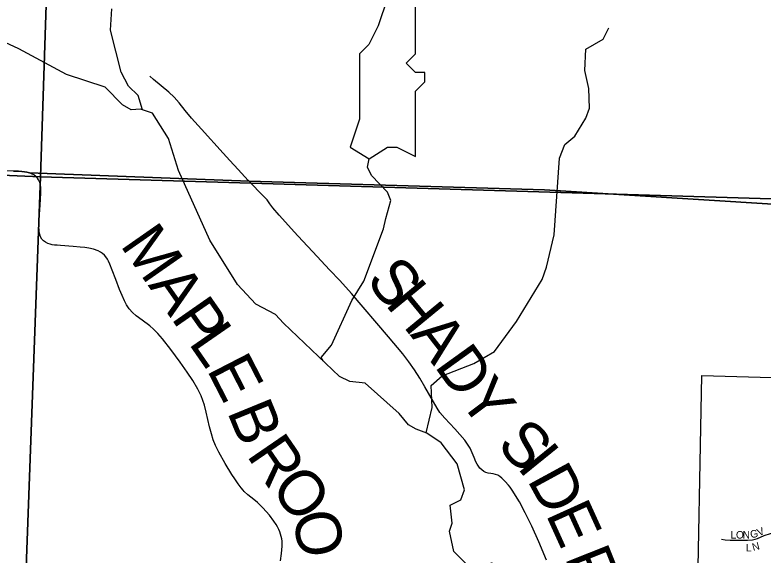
# Model space of a CAD drawing. Extents: x 0 to 34, y 0 to 22.
# Drawn here: x 26.645 to 27.584, y 17.84 to 18.518 of the extents above; entities that cross this region are included whole.
import ezdxf

# ---------------------------------------------------------------- set-up
doc = ezdxf.new("R2010")
doc.units = 0
for name, color, linetype in [('GM_X_City_Street', 7, 'Continuous'), ('GM_X_City_Street_Text', 7, 'Continuous'), ('GM_X_Corporation', 7, 'Continuous'), ('GM_X_Minor_Lake', 7, 'Continuous'), ('GM_X_Minor_River', 7, 'Continuous'), ('GM_X_Section', 7, 'Continuous'), ('GM_X_Township', 7, 'Continuous'), ('GM_X_Township_Road', 7, 'Continuous'), ('GM_X_Township_Road_Text', 7, 'Continuous')]:
    doc.layers.add(name, color=color, linetype=linetype)

msp = doc.modelspace()

# ---------------------------------------------------------------- linework, layer by layer
at = {"layer": 'GM_X_City_Street'}
msp.add_lwpolyline([(27.5316, 17.86006), (27.53621, 17.8594), (27.54244, 17.859), (27.55182, 17.85887), (27.56434, 17.85906), (27.57056, 17.85951), (27.57361, 17.86008), (27.57659, 17.86099), (27.58524, 17.86465), (27.59314, 17.86742), (27.59554, 17.86765), (27.60988, 17.86768), (27.63074, 17.8673)], dxfattribs=at)
at = {"layer": 'GM_X_Corporation'}
msp.add_lwpolyline([(26.90696, 16.92457), (26.90869, 17.23113), (26.9676, 17.24455), (26.96758, 17.23868), (27.13632, 17.27124), (27.45355, 17.35652), (27.45221, 17.36927), (27.4769, 17.37407), (27.40895, 17.45881), (27.41908, 17.4656), (27.42835, 17.45306), (27.5213, 17.52673), (27.43555, 17.68311), (27.50076, 17.73762), (27.50706, 18.06564), (27.60948, 18.06256)], dxfattribs=at)
msp.add_lwpolyline([(26.90696, 16.92457), (26.90869, 17.23113), (26.9676, 17.24455), (26.96758, 17.23868), (27.13632, 17.27124), (27.45355, 17.35652), (27.45221, 17.36927), (27.4769, 17.37407), (27.40895, 17.45881), (27.41908, 17.4656), (27.42835, 17.45306), (27.5213, 17.52673), (27.43555, 17.68311), (27.50076, 17.73762), (27.50706, 18.06564), (27.60948, 18.06256)], dxfattribs=at)
at = {"layer": 'GM_X_Minor_Lake'}
for points in [[(27.12245, 18.75022), (27.11268, 18.75011), (27.11268, 18.73841), (27.10097, 18.72671), (27.10097, 18.71501), (27.10097, 18.6799), (27.10097, 18.66819), (27.10096, 18.64479), (27.10096, 18.62138), (27.10096, 18.60968), (27.10096, 18.58627), (27.10095, 18.56287), (27.11266, 18.53946), (27.10095, 18.50437), (27.08924, 18.48097), (27.07754, 18.46926), (27.07754, 18.44586), (27.07753, 18.42245), (27.07753, 18.38734), (27.06582, 18.35223), (27.08951, 18.33736)], [(27.08951, 18.33736), (27.11264, 18.35223), (27.12433, 18.35223), (27.14773, 18.34053), (27.14773, 18.35223), (27.14773, 18.37563), (27.14774, 18.39904), (27.14774, 18.41074), (27.14774, 18.42245), (27.15944, 18.43415), (27.15945, 18.44585), (27.14774, 18.44585), (27.13604, 18.45756), (27.14774, 18.46926), (27.14775, 18.48096), (27.14775, 18.49266), (27.14775, 18.51605), (27.14775, 18.53946)]]:
    msp.add_lwpolyline(points, dxfattribs=at)
at = {"layer": 'GM_X_Minor_River'}
for points in [[(26.80545, 18.39887), (26.79994, 18.41687), (26.78776, 18.42856), (26.77856, 18.44595), (26.76538, 18.49898), (26.76675, 18.52554)], [(27.1957, 17.8449), (27.19025, 17.87029), (27.19361, 17.88017), (27.19121, 17.90291), (27.20481, 17.90943), (27.20929, 17.92198), (27.20001, 17.95492), (27.18016, 17.98098), (27.1619, 17.99339), (27.14862, 17.99824), (27.13911, 18.0035), (27.12729, 18.01785), (27.08463, 18.05591), (27.0653, 18.05807), (27.05238, 18.06445), (26.98228, 18.13118), (26.97237, 18.14212), (26.94767, 18.15488), (26.92442, 18.17977), (26.89, 18.23533), (26.85049, 18.32272), (26.83814, 18.36285), (26.81788, 18.3946), (26.80269, 18.39982), (26.79133, 18.399), (26.78031, 18.40538), (26.75858, 18.42725), (26.70999, 18.44329), (26.65032, 18.47556), (26.59372, 18.50141)], [(27.31194, 18.20134), (27.32189, 18.24208), (27.32843, 18.33844), (27.33506, 18.35558), (27.34743, 18.36595), (27.36157, 18.38847), (27.36597, 18.40103), (27.36533, 18.42566), (27.36017, 18.44835), (27.36141, 18.47491), (27.38321, 18.48765), (27.39025, 18.50176)], [(27.03184, 18.084), (27.02951, 18.08821), (27.04231, 18.10383), (27.06776, 18.15973), (27.08316, 18.1841), (27.10781, 18.24948), (27.11038, 18.26277), (27.1167, 18.28518), (27.11247, 18.29578), (27.09265, 18.31652), (27.08767, 18.32711), (27.08951, 18.33736)], [(27.1611, 17.99368), (27.16855, 18.02529), (27.16726, 18.05297), (27.18121, 18.06518), (27.22091, 18.08058), (27.24697, 18.09553), (27.27442, 18.13323), (27.30672, 18.18614), (27.31194, 18.20134)], [(27.1957, 17.8449), (27.21128, 17.8294), (27.22037, 17.82946), (27.22873, 17.82534), (27.23479, 17.82614), (27.24309, 17.83074), (27.2484, 17.82926), (27.25147, 17.82435), (27.26898, 17.81118), (27.28113, 17.80557), (27.28947, 17.80448), (27.29407, 17.79654), (27.29646, 17.77949), (27.29884, 17.76282), (27.30719, 17.75983)]]:
    msp.add_lwpolyline(points, dxfattribs=at)
at = {"layer": 'GM_X_Section'}
for points in [[(25.7174, 19.34531), (26.71012, 19.30514), (26.67748, 18.31474), (25.68285, 18.35754)], [(27.70209, 19.27644), (27.6773, 18.28453), (26.67748, 18.31474), (26.71012, 19.30514)], [(26.67748, 18.31474), (26.63943, 17.27671), (26.13693, 17.28272), (26.13573, 17.24141), (25.63163, 17.25763), (25.68285, 18.35754)], [(26.67748, 18.31474), (27.6773, 18.28453), (27.62712, 17.24067), (26.63943, 17.27671)]]:
    msp.add_lwpolyline(points, close=True, dxfattribs=at)
at = {"layer": 'GM_X_Township'}
for points in [[(26.64338, 18.32213), (26.64994, 18.32195), (26.65415, 18.32164), (26.6574, 18.3212), (26.66046, 18.32066), (26.66345, 18.31987), (26.93903, 18.30939), (27.3097, 18.29835), (27.60273, 18.28017), (27.85085, 18.27245), (28.03523, 18.26605), (28.13527, 18.2617), (28.25997, 18.25738), (28.66555, 18.2443), (28.72626, 19.93416)], [(28.59551, 16.41415), (28.59908, 16.58872), (28.59988, 16.61088), (28.63677, 17.49807), (28.63701, 17.50604), (28.6433, 17.85758), (28.66555, 18.2443), (28.25997, 18.25738), (28.13527, 18.2617), (28.03523, 18.26605), (27.85085, 18.27245), (27.60273, 18.28017), (27.3097, 18.29835), (26.93903, 18.30939), (26.66345, 18.31987), (26.66046, 18.32066), (26.6574, 18.3212), (26.65415, 18.32164), (26.64994, 18.32195), (26.64338, 18.32213)]]:
    msp.add_lwpolyline(points, dxfattribs=at)
at = {"layer": 'GM_X_Township_Road'}
for points in [[(26.93842, 18.31003), (26.93803, 18.31043), (26.92529, 18.32403), (26.91477, 18.33545), (26.9064, 18.34462), (26.87939, 18.37463), (26.86691, 18.38848), (26.85886, 18.39795), (26.85115, 18.40771), (26.84503, 18.41473), (26.83832, 18.42119), (26.82875, 18.42911), (26.81918, 18.43705), (26.81459, 18.44121)], [(26.66534, 18.31912), (26.66346, 18.31987), (26.66045, 18.32066), (26.6574, 18.3212), (26.65415, 18.32164), (26.64994, 18.32195), (26.64337, 18.32213), (26.5923, 18.32397), (26.5706, 18.32489), (26.55514, 18.32585), (26.53747, 18.3271), (26.52526, 18.32795), (26.51587, 18.32844), (26.50008, 18.32926), (26.48991, 18.32965), (26.48619, 18.33005)], [(26.93173, 17.92155), (26.93151, 17.9218), (26.92894, 17.92474), (26.92519, 17.92968), (26.92099, 17.93589), (26.91722, 17.94156), (26.90886, 17.95504), (26.90101, 17.9694), (26.89689, 17.97771), (26.89403, 17.98498), (26.89186, 17.99235), (26.88948, 18.00135), (26.88532, 18.0195), (26.88298, 18.0285), (26.88105, 18.03439), (26.87892, 18.04026), (26.87461, 18.04862), (26.86831, 18.05918), (26.86152, 18.06958), (26.85242, 18.08215), (26.84089, 18.09825), (26.83065, 18.11146), (26.82471, 18.11847), (26.81932, 18.12387), (26.81473, 18.12791), (26.80504, 18.13498), (26.79729, 18.14038), (26.79261, 18.14477), (26.78875, 18.14917), (26.78546, 18.15413), (26.78271, 18.15935), (26.77968, 18.16595), (26.77666, 18.17338), (26.77176, 18.18592), (26.76727, 18.19777), (26.76445, 18.20512), (26.76274, 18.20909), (26.76128, 18.21174), (26.75951, 18.21429), (26.75751, 18.21665), (26.75522, 18.21874), (26.75265, 18.22045), (26.74987, 18.22182), (26.74402, 18.22392), (26.73799, 18.22538), (26.73308, 18.22607), (26.72697, 18.22663), (26.71859, 18.22743), (26.70251, 18.22856), (26.69843, 18.2289), (26.69503, 18.22924), (26.69209, 18.22969), (26.68937, 18.23037), (26.68645, 18.23138), (26.68363, 18.23266), (26.68112, 18.23444), (26.67918, 18.2366), (26.67755, 18.23946), (26.67654, 18.24237), (26.6759, 18.2454), (26.67555, 18.24849), (26.67539, 18.25159), (26.67544, 18.25779), (26.67642, 18.27327), (26.67738, 18.28623), (26.67786, 18.29516), (26.67786, 18.30091), (26.67724, 18.3046), (26.67642, 18.30778), (26.67499, 18.31087), (26.67355, 18.31312), (26.6714, 18.31538), (26.66902, 18.31719), (26.66633, 18.31873), (26.66534, 18.31912)], [(27.31225, 17.83388), (27.30267, 17.85684), (27.2937, 17.87667), (27.2855, 17.89343), (27.27818, 17.90714), (27.27334, 17.91507), (27.26996, 17.92027), (27.26651, 17.92542), (27.26457, 17.92786), (27.26037, 17.9324), (27.25599, 17.93672), (27.25367, 17.93875), (27.25109, 17.94041), (27.24824, 17.94154), (27.2452, 17.94208), (27.2421, 17.94243), (27.23904, 17.94299), (27.2361, 17.94394), (27.23336, 17.94534), (27.23087, 17.94716), (27.22865, 17.94932), (27.22668, 17.95175), (27.22499, 17.95436), (27.22356, 17.95711), (27.22118, 17.96286), (27.21775, 17.97154), (27.21638, 17.97432), (27.21319, 17.97964), (27.2095, 17.98463), (27.20348, 17.99173), (27.19718, 17.9986), (27.19077, 18.00537), (27.18444, 18.01222), (27.17847, 18.01935), (27.17495, 18.02445), (27.17014, 18.03242), (27.15946, 18.0514), (27.15319, 18.06214), (27.1465, 18.07262), (27.13933, 18.08277), (27.13169, 18.09259), (27.11373, 18.11405), (27.06739, 18.16851), (27.0528, 18.18466), (27.04004, 18.19824), (27.0188, 18.2209), (27.00612, 18.23457), (26.99558, 18.246), (26.98096, 18.2621), (26.97681, 18.26668), (26.96887, 18.27608), (26.96515, 18.28092), (26.96175, 18.28589), (26.95095, 18.297), (26.93903, 18.30939), (26.93842, 18.31003)], [(26.97865, 17.83314), (26.9798, 17.84247), (26.98046, 17.85141), (26.98053, 17.85448), (26.98037, 17.85755), (26.97996, 17.8606), (26.97933, 17.86362), (26.97851, 17.86659), (26.97746, 17.8695), (26.97645, 17.87224), (26.97477, 17.8757), (26.97289, 17.87874), (26.96995, 17.88293), (26.96482, 17.89031), (26.95613, 17.89966), (26.94957, 17.90618), (26.94481, 17.9101), (26.9376, 17.91593), (26.93307, 17.92013), (26.93173, 17.92155)]]:
    msp.add_lwpolyline(points, dxfattribs=at)

# ---------------------------------------------------------------- texts
at = {"layer": 'GM_X_City_Street_Text'}
for s, rotation, p in [('V', 23.73514, (27.57866, 17.86372)), ('L', 0.13655, (27.54306, 17.86095)), ('O', 0.10926, (27.54973, 17.86096)), ('N', 0.13875, (27.55807, 17.86098)), ('G', 12.8216, (27.56868, 17.86126)), ('N', 15.57616, (27.57146, 17.84534)), ('L', 1.12062, (27.56227, 17.84483))]:
    msp.add_text(s, height=0.00947, rotation=rotation, dxfattribs=at).set_placement(p)
at = {"layer": 'GM_X_Township_Road_Text'}
for s, rotation, p in [('M', 304.92548, (26.7764, 18.22944)), ('S', 309.63644, (27.08433, 18.18439)), ('A', 304.92878, (26.8117, 18.17888)), ('H', 309.47114, (27.10876, 18.1549)), ('P', 304.90522, (26.84033, 18.13789)), ('L', 304.72904, (26.86224, 18.1065)), ('A', 307.75295, (27.14026, 18.11666)), ('D', 305.75957, (27.17056, 18.07755)), ('E', 297.24356, (26.88544, 18.07325)), ('Y', 306.90853, (27.20052, 18.03597)), ('B', 292.31033, (26.911, 18.02043)), ('S', 314.88716, (27.24805, 17.97659)), ('R', 304.44865, (26.93496, 17.96571)), ('I', 309.02798, (27.27407, 17.95057)), ('D', 298.54476, (27.28724, 17.93473)), ('O', 308.9501, (26.96426, 17.92332)), ('E', 294.43332, (27.31065, 17.89177)), ('O', 281.4564, (26.99266, 17.8909)), ('R', 291.70865, (27.3346, 17.83755))]:
    msp.add_text(s, height=0.05682, rotation=rotation, dxfattribs=at).set_placement(p)

doc.saveas('drawing.dxf')
